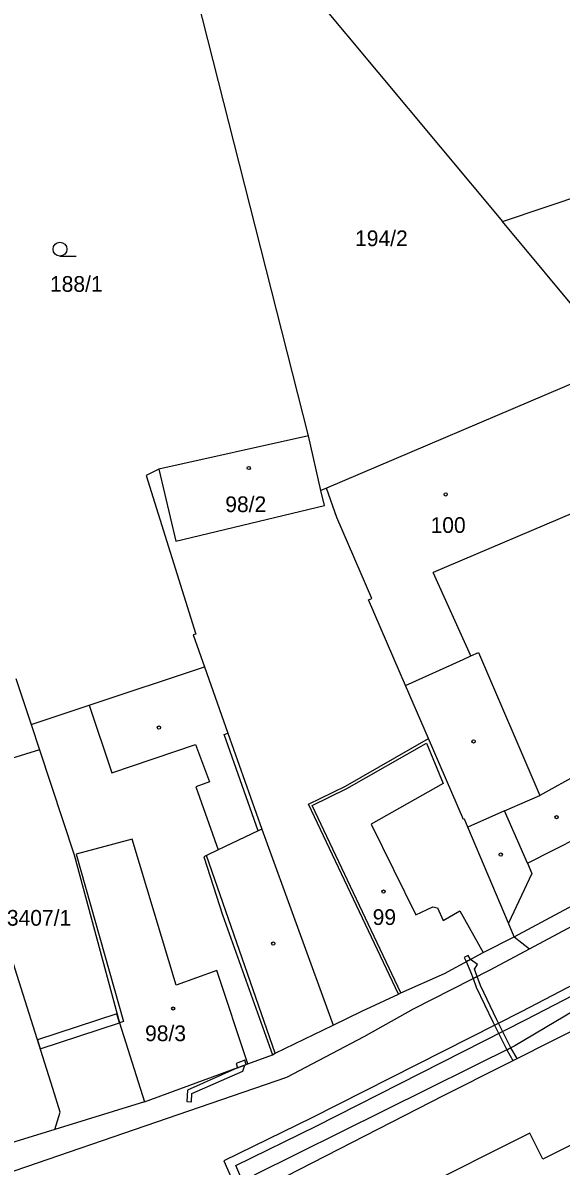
# Model space of a CAD drawing. Extents: x -776734 to -748832, y -1118122 to -976986.
# Drawn here: x -753044.6 to -752986.4, y -1115568.5 to -1115444.8 of the extents above; entities that cross this region are included whole.
import ezdxf

# ---------------------------------------------------------------- set-up
doc = ezdxf.new("R2010")
doc.units = 0
for name, color, linetype in [('KM_Hranice parcel', 7, 'Continuous'), ('KM_Parcelní čísla', 7, 'Continuous'), ('KM_Vnitřní kresba', 7, 'Continuous'), ('KM_Věcná břemena k části', 7, 'Continuous'), ('KM_Značky budov', 7, 'Continuous'), ('KM_Značky kultur', 7, 'Continuous')]:
    doc.layers.add(name, color=color, linetype=linetype)

msp = doc.modelspace()

# ---------------------------------------------------------------- linework, layer by layer
at = {"layer": 'KM_Hranice parcel'}
for p, q in [((-753016.65, -1115437.56), (-752992.73, -1115466.29)), ((-753013.7, -1115489.49), (-753026.35, -1115439.58)), ((-752992.73, -1115466.29), (-752970, -1115458.62)), ((-752980.02, -1115481.57), (-752992.73, -1115466.29)), ((-753045.31, -1115515.73), (-753043.66, -1115520.72)), ((-753043.66, -1115520.72), (-753042.76, -1115523.46)), ((-753042.76, -1115523.46), (-753052.01, -1115526.27)), ((-752991.45, -1115543.69), (-752979.18, -1115537.03)), ((-752989.81, -1115544.97), (-752978.37, -1115538.88)), ((-752991.45, -1115543.69), (-752989.81, -1115544.97)), ((-753031.4, -1115561.54), (-753041.11, -1115564.53)), ((-753041.11, -1115564.53), (-753061.42, -1115570.77))]:
    msp.add_line(p, q, dxfattribs=at)
for points in [[(-752976.46, -1115489.36), (-752980.78, -1115491.41), (-752984.32, -1115483.46), (-753011.75, -1115495.13)], [(-753013.7, -1115489.49), (-753029.87, -1115493.09), (-753031.25, -1115493.76), (-753025.85, -1115510.93), (-753026.15, -1115511.01), (-753024.93, -1115514.46)], [(-753011.75, -1115495.13), (-753012.34, -1115495.38), (-753013.7, -1115489.49)], [(-752923.31, -1115491.48), (-752928.94, -1115502.31), (-752937.29, -1115515.53), (-752954.67, -1115532.77), (-752960.09, -1115536.91), (-752991.37, -1115555.48), (-753019.55, -1115569.44)], [(-753000.71, -1115522.23), (-753003.19, -1115516.5), (-753007.2, -1115507.23), (-753006.83, -1115507.07), (-753010.61, -1115498.31), (-753011.75, -1115495.13)], [(-753043.66, -1115520.72), (-753037.4, -1115518.6), (-753024.93, -1115514.46)], [(-753024.93, -1115514.46), (-753022.39, -1115521.65), (-753018.73, -1115532.02), (-753019.11, -1115532.2), (-753023.46, -1115534.28), (-753024.72, -1115534.88), (-753024.99, -1115535.01), (-753022.99, -1115541.28), (-753017.58, -1115556.44)], [(-753003.95, -1115549.87), (-753013.7, -1115529.34), (-753009.68, -1115527.37), (-753000.71, -1115522.23)], [(-752991.45, -1115543.69), (-752992.08, -1115542.21), (-752996.47, -1115531.82), (-752996.83, -1115530.96), (-752996.93, -1115530.99), (-753000.71, -1115522.23)], [(-753042.76, -1115523.46), (-753039, -1115534.82), (-753034.13, -1115552.97), (-753031.4, -1115561.54)], [(-753041.11, -1115564.53), (-753040.52, -1115562.65), (-753041.33, -1115560.07), (-753052.01, -1115526.27)], [(-753018.91, -1115571.01), (-752999.02, -1115560.81), (-752966.63, -1115544.51), (-752965.91, -1115545.71)], [(-753003.95, -1115549.87), (-753003.69, -1115549.74), (-752998.99, -1115547.63), (-752994.8, -1115545.38), (-752991.45, -1115543.69)], [(-753117.71, -1115593.89), (-753059.47, -1115573.8), (-753016.02, -1115558.84), (-753007.66, -1115554.44), (-753002.34, -1115551.48), (-752994.05, -1115547.25), (-752989.81, -1115544.97)], [(-753017.58, -1115556.44), (-753017.28, -1115556.25), (-753011.01, -1115553.22), (-753007.92, -1115551.73), (-753003.95, -1115549.87)], [(-753031.4, -1115561.54), (-753020.26, -1115557.43), (-753017.58, -1115556.44)]]:
    msp.add_lwpolyline(points, dxfattribs=at)
at = {"layer": 'KM_Vnitřní kresba'}
for p, q in [((-753029.87, -1115493.09), (-753028.01, -1115500.87)), ((-752979.06, -1115495.27), (-753000.2, -1115504.25)), ((-753011.96, -1115497.03), (-753012.34, -1115495.38)), ((-753028.01, -1115500.87), (-753011.96, -1115497.03)), ((-752996.15, -1115513.29), (-753000.2, -1115504.25)), ((-753003.19, -1115516.5), (-752996.95, -1115513.66)), ((-752996.95, -1115513.66), (-752996.15, -1115513.29)), ((-752996.15, -1115513.29), (-752995.32, -1115512.93)), ((-752995.32, -1115512.93), (-752988.69, -1115528.38)), ((-753037.4, -1115518.6), (-753034.93, -1115525.92)), ((-753022.79, -1115521.79), (-753022.39, -1115521.65)), ((-753019.11, -1115532.2), (-753022.79, -1115521.79)), ((-753034.93, -1115525.92), (-753025.9, -1115522.88)), ((-753025.9, -1115522.88), (-753024.37, -1115526.91)), ((-753009.55, -1115527.64), (-753000.92, -1115522.71)), ((-753000.92, -1115522.71), (-752999.14, -1115527.09)), ((-753024.37, -1115526.91), (-753025.88, -1115527.45)), ((-753025.88, -1115527.45), (-753023.46, -1115534.28)), ((-752999.14, -1115527.09), (-753006.93, -1115531.47)), ((-753013.3, -1115529.48), (-753009.55, -1115527.64)), ((-752990.84, -1115529.33), (-752988.69, -1115528.38)), ((-753003.69, -1115549.74), (-753013.3, -1115529.48)), ((-752992.49, -1115530.06), (-752990.84, -1115529.33)), ((-752992.49, -1115530.06), (-752996.47, -1115531.82)), ((-752990.02, -1115535.71), (-752992.49, -1115530.06)), ((-753018.73, -1115532.02), (-753011.01, -1115553.22)), ((-753006.93, -1115531.47), (-753002.07, -1115541.31)), ((-753032.73, -1115533.12), (-753038.79, -1115534.73)), ((-753027.98, -1115548.92), (-753032.73, -1115533.12)), ((-753038.79, -1115534.73), (-753033.7, -1115552.83)), ((-753017.28, -1115556.25), (-753024.72, -1115534.88)), ((-752990.02, -1115535.71), (-752989.55, -1115536.81)), ((-752989.55, -1115536.81), (-752992.08, -1115542.21)), ((-753002.07, -1115541.31), (-753000.25, -1115540.44)), ((-753000.25, -1115540.44), (-752999.75, -1115540.54)), ((-752999.75, -1115540.54), (-752999.13, -1115541.9)), ((-752999.13, -1115541.9), (-752997.31, -1115540.88)), ((-752997.31, -1115540.88), (-752994.8, -1115545.38)), ((-753023.61, -1115547.3), (-753027.98, -1115548.92)), ((-753020.26, -1115557.43), (-753023.61, -1115547.3)), ((-753033.7, -1115552.83), (-753034.13, -1115552.97)), ((-752979.78, -1115563.42), (-752988.37, -1115567.71)), ((-752989.76, -1115564.92), (-753008.53, -1115574.29)), ((-752988.37, -1115567.71), (-752989.76, -1115564.92))]:
    msp.add_line(p, q, dxfattribs=at)
msp.add_lwpolyline([(-752990.02, -1115535.71), (-752981.63, -1115531.45), (-752984.41, -1115526.02), (-752988.69, -1115528.38)], dxfattribs=at)
at = {"layer": 'KM_Věcná břemena k části'}
for points in [[(-752996.63, -1115546.36), (-752996.19, -1115546.13), (-752996.43, -1115545.69), (-752996.87, -1115545.92)], [(-752996.15, -1115547.53), (-752995.9, -1115548.2), (-752995.46, -1115547.97), (-752995.76, -1115547.18), (-752995.4, -1115546.65), (-752996.19, -1115546.13), (-752996.63, -1115546.36)], [(-752992.24, -1115555.91), (-752991.8, -1115555.69), (-752993.32, -1115552.64), (-752995.09, -1115548.93), (-752995.46, -1115547.97), (-752995.9, -1115548.2), (-752995.55, -1115549.13), (-752993.76, -1115552.86)], [(-753034.13, -1115552.97), (-753034.39, -1115552.02), (-753042.99, -1115554.83), (-753042.69, -1115555.78)], [(-752991.59, -1115557.07), (-752991.14, -1115556.85), (-752991.8, -1115555.69), (-752992.24, -1115555.91)], [(-753021.35, -1115557.83), (-753020.58, -1115557.55), (-753020.41, -1115557.49), (-753020.58, -1115557.02), (-753021.52, -1115557.36)], [(-753026.29, -1115560.61), (-753020.8, -1115558.22), (-753020.58, -1115557.55), (-753021.35, -1115557.83), (-753026.77, -1115560.27), (-753026.84, -1115561.48), (-753026.35, -1115561.51)]]:
    msp.add_lwpolyline(points, close=True, dxfattribs=at)
for points in [[(-752982.48, -1115547.5), (-752990.64, -1115551.74), (-753013.32, -1115563.24), (-753022.85, -1115567.92), (-753021.81, -1115570.28)], [(-753020.88, -1115569.94), (-753021.55, -1115568.4), (-753012.87, -1115564.14), (-752990.24, -1115552.67), (-752981.96, -1115548.35)]]:
    msp.add_lwpolyline(points, dxfattribs=at)
at = {"layer": 'KM_Značky budov'}
for centre in [(-753020.1468, -1115492.9592), (-752998.8568, -1115495.8192), (-753029.8568, -1115521.0392), (-752995.8468, -1115522.5392), (-752986.8668, -1115530.7292), (-752992.9068, -1115534.7792), (-753005.5768, -1115538.7792), (-753017.4968, -1115544.3992), (-753028.3168, -1115551.4292)]:
    msp.add_circle(centre, 0.175, dxfattribs=at)
at = {"layer": 'KM_Značky kultur'}
msp.add_line((-753040.553, -1115470.04), (-753038.803, -1115470.04), dxfattribs=at)
msp.add_circle((-753040.5529, -1115469.2898), 0.75, dxfattribs=at)

# ---------------------------------------------------------------- texts
at = {"layer": 'KM_Parcelní čísla'}
for s, p in [('194/2', (-753008.65, -1115468.96)), ('188/1', (-753041.63, -1115473.9)), ('98/2', (-753022.68, -1115497.73)), ('100', (-753000.49, -1115499.98)), ('3407/1', (-753046.29, -1115542.47)), ('99', (-753006.75, -1115542.39)), ('98/3', (-753031.35, -1115554.96))]:
    msp.add_text(s, height=1.7, dxfattribs=at).set_placement(p)

doc.saveas('drawing.dxf')
